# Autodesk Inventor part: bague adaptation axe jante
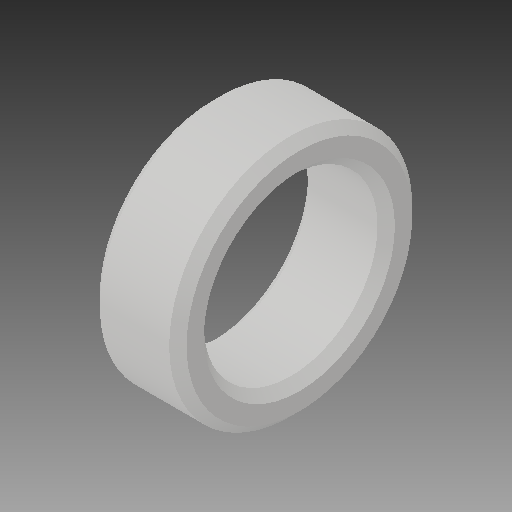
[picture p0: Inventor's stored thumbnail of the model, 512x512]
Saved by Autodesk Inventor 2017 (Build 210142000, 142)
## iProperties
Part Number: bague adaptation axe jante
Material: Générique
Document SubType Name: Modeling
Designer: ficho
Density: 1 g/cm^3
Appearance: Par défaut
Mass: 0.358142 g
Surface Area: 4.8362 cm^2
Volume: 0.358142 cm^3
Author: ficho
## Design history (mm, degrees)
sketch "Esquisse1"
  geometry: L1 (0, 7)-(-5, 7); L2 (-5, 7)-(-5, 5); L3 (-5, 5)-(0, 5); L4 (0, 5)-(0, 7); L5 (-6, 0)-(1, 0) reference; 1 further point
  constraints: 8 end point, 2 parallel, 1 horizontal, 1 perpendicular
  dimensions: "d0" = 5 distance of L3.end L2.end; "d1" = 2 distance of L2.end L1.end; "d2" = 5 distance from line of L3 point (0, 0)
revolve "Révolution1" sketch "Esquisse1" stored, may be unused: angle "d3" = 90 deg
chamfer "Chanfrein1" distance "d4" = 0.5; stored, may be unused: second distance "d5" = 2, angle "d6" = 45 deg
node "Solide1"
